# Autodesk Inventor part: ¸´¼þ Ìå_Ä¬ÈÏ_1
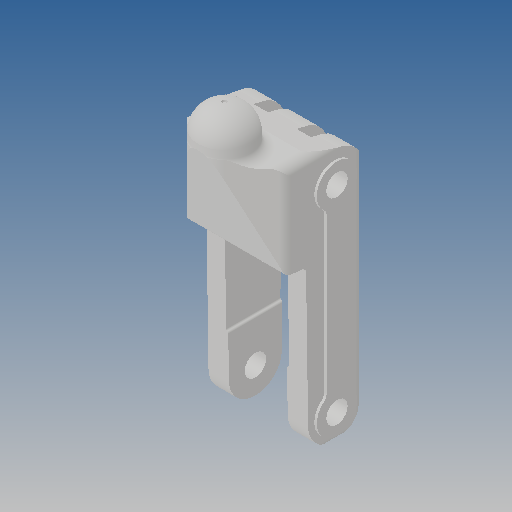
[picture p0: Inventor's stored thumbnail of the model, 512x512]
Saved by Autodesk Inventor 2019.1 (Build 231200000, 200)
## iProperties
Created: 2012-10
Part Number: ¸´¼þ Ìå_Ä¬ÈÏ_1
Material: Ogólny
Document SubType Name: Modeling
Designer: CADENGINEERING4
Density: 1 g/cm^3
Appearance: Domyślna
Author: CADENGINEERING4
Revision Number: ÈÎºÎ
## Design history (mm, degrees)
feature "NONE"
node "Bryła1"
